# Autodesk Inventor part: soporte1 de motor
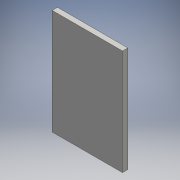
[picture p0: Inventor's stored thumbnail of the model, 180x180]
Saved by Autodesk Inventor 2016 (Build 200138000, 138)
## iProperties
Created: 2016-06
Part Number: soporte1 de motor
Material: Genérico
Document SubType Name: Modeling
Designer: adm
Density: 1 g/cm^3
Appearance: Valor por defecto
Author: adm
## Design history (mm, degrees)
sketch "Boceto1"
  geometry: L1 (-20, -1.5)-(20, -1.5); L2 (20, -1.5)-(20, 1.5); L3 (20, 1.5)-(-20, 1.5); L4 (-20, 1.5)-(-20, -1.5); L5 (-20, -1.5)-(20, 1.5); L6 (20, -1.5)-(-20, 1.5); 1 further point
  constraints: 12 end point, 2 midpoint, 2 parallel, 1 horizontal, 1 perpendicular
  dimensions: "d0" = 40 distance of L3.end L2.end; "d1" = 3 distance of L2.end L1.end
extrude "Extrusión1" new body sketch "Boceto1" distance "d2" = 60; taper "d3" = 0 deg
node "Sólido1"
